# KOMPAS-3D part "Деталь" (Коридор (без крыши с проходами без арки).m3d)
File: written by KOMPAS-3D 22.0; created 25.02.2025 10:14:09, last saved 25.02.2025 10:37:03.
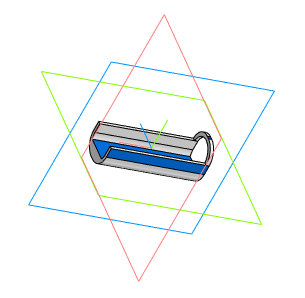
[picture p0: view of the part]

Document properties: Автор: Пользователь Windows; Полное имя файла: C:\Users\Student\Documents\Картошечка\База Сабнатика\Коридор\Коридор (без крфши с проходами без арки).m3d

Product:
- Body: Тело 1
    Масса: 0.008372
- Part/product: Деталь
    Масса: 0.008187

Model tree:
1. Эскиз:1
2. Элемент выдавливания:1
     Расстояние 1 = 30
3. Эскиз:2  (with: Элемент выдавливания:1)
4. Элемент выдавливания:2
     Расстояние 2 = 5
5. Оболочка:1  (with: Элемент выдавливания:2)
     Толщина стенки 2 = 1
6. Эскиз:3  (with: Оболочка:1)
7. Элемент выдавливания:3
     Расстояние 1 = 28
8. Эскиз:4  (with: Оболочка:1)
9. Элемент выдавливания:4
     Расстояние 1 = 32; Расстояние 2 = 1
10. Элемент выдавливания:5  (with: Оболочка:1)
     Расстояние 2 = 1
